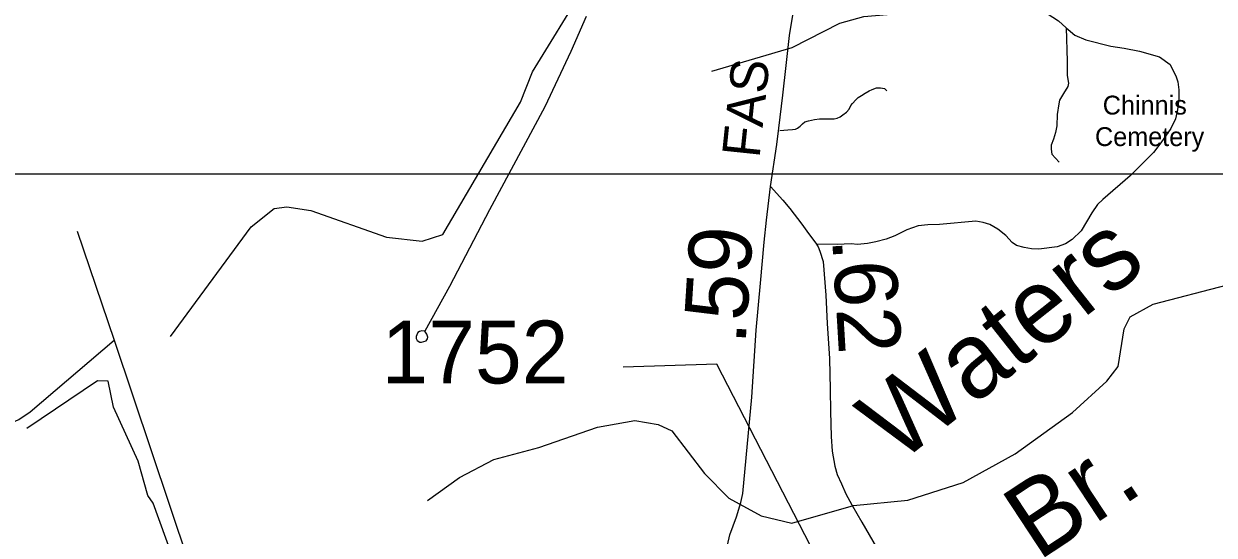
# Model space of a CAD drawing. Extents: x 2225501 to 2309677, y 165449 to 227696.
# Drawn here: x 2252503 to 2261977, y 188364 to 192432 of the extents above; entities that cross this region are included whole.
import ezdxf

# ---------------------------------------------------------------- set-up
doc = ezdxf.new("R2010")
doc.units = 0
for name, color, linetype in [('E_RDY_CMT_EOP', 7, 'Continuous'), ('Exist Vegetation Text', 7, 'Continuous'), ('Old_Level_3', 7, 'Continuous'), ('Old_Level_33', 7, 'Continuous'), ('Old_Level_50', 7, 'Continuous'), ('P_HYD_Drop_Inlet_Grate_2_Narrow_Slots_and_Sag_Grates_840_24_54_Dia_CELL', 7, 'Continuous'), ('P_HYD_Endwall_838_01_18_Dia_Single-Top_CELL', 7, 'Continuous'), ('P_HYD_Pipe_Pipe_Removal', 7, 'Continuous'), ('P_RDY_Dimension_Text', 7, 'Continuous'), ('Prop Support', 7, 'Continuous'), ('Scratch_Level_1', 7, 'Continuous'), ('Scratch_Level_7', 7, 'Continuous'), ('Typical Terminator CELL', 7, 'Continuous')]:
    doc.layers.add(name, color=color, linetype=linetype)

msp = doc.modelspace()

# ---------------------------------------------------------------- linework, layer by layer
at = {"layer": 'Old_Level_3'}
for p, q in [((2252926.7, 190782.9), (2253221.5, 189915.8)), ((2253221.5, 189915.8), (2253929.5, 187811.9))]:
    msp.add_line(p, q, dxfattribs=at)
for points in [[(2258940.7, 193185.2), (2259378.5, 193157.6), (2259462.9, 193157.6), (2259535.6, 193148.9), (2259608.3, 193119.8), (2259695.5, 193079.1), (2259983.5, 192924.9), (2260184.1, 192817.2), (2260285.9, 192756.1), (2260422.6, 192663), (2260737.8, 192456.1), (2260797.9, 192401.8)], [(2256979, 192491.4), (2256855.4, 192212.6), (2256649, 191771), (2256208, 190953.7), (2255891, 190343.5), (2255694.1, 189986)], [(2260797.9, 192401.8), (2260814.4, 192386.8), (2260868.8, 192343.2), (2260955, 192303.9), (2261155.4, 192255.6), (2261261.4, 192238.6), (2261383.5, 192213.6), (2261541.9, 192170.9), (2261626.4, 192109.5), (2261675.1, 192012), (2261687.5, 191972.1), (2261696.1, 191906.2), (2261694.5, 191838.2), (2261685.4, 191748.2), (2261668, 191676), (2261632.5, 191599.9), (2261553.5, 191485.3), (2261494.2, 191408.8), (2261307.6, 191223.3), (2261089.4, 191035.6), (2261047.6, 190995.2), (2261004.2, 190928.9), (2260917.4, 190784.2), (2260846, 190715.6), (2260792.4, 190681.3), (2260726.6, 190658.8), (2260580.8, 190639.6), (2260522.7, 190643.1), (2260464.7, 190652.7), (2260404.7, 190670), (2260368.3, 190693.7), (2260318, 190747.3), (2260255.6, 190798.9), (2260191.4, 190836.4), (2260139.3, 190852), (2260081.1, 190861.5), (2259791.4, 190835.1), (2259697.6, 190832.4), (2259619.7, 190825.7), (2259529.9, 190792.9), (2259436.4, 190746.3), (2259366.7, 190719.6), (2259284.9, 190697), (2259219, 190684.5), (2259137.1, 190677.7), (2259087, 190681.3), (2258975.1, 190676.5), (2258811.2, 190679.1)], [(2260797.9, 192401.8), (2260808, 192136.4), (2260808, 192020.1), (2260816.7, 191959), (2260810.9, 191932.8), (2260778.9, 191877.5), (2260746.9, 191825.1), (2260741.1, 191796), (2260726.5, 191711.7), (2260723.6, 191621.5), (2260714.9, 191569.1), (2260697.4, 191513.8), (2260680, 191467.3), (2260680, 191435.3), (2260685.8, 191394.6), (2260744, 191330.6)], [(2258520.5, 191583.4), (2258583.1, 191588.8), (2258620.9, 191591.7), (2258644.2, 191594.6), (2258660.2, 191601.9), (2258680.5, 191617.9), (2258700.9, 191636.8), (2258719.8, 191652.8), (2258748.9, 191661.5), (2258796.9, 191670.2), (2258836.1, 191676), (2258879.8, 191677.5), (2258923.4, 191677.5), (2258952.5, 191677.5), (2258977.2, 191681.9), (2259000.5, 191692), (2259022.3, 191708), (2259049.9, 191729.9), (2259071.7, 191754.6), (2259086.3, 191782.2), (2259097.9, 191799.7), (2259124.1, 191828.8), (2259144.4, 191846.2), (2259169.1, 191862.2), (2259199.7, 191879.7), (2259230.2, 191898.6), (2259254.9, 191910.2), (2259289.8, 191921.9), (2259320.4, 191923.3), (2259353.8, 191917.5), (2259372.7, 191898.6)], [(2255694.1, 189986), (2255669.9, 189989.6), (2255652, 189983.6), (2255640.1, 189975.4), (2255630.4, 189959.4), (2255626.5, 189945.3), (2255626.6, 189929.3), (2255634.7, 189913.6), (2255654.8, 189899.6), (2255666.8, 189899.7), (2255704.6, 189910), (2255716.5, 189926.2), (2255718.4, 189940.1), (2255710.2, 189962.1), (2255694.1, 189986)], [(2252411.3, 189261.4), (2252463, 189283.9), (2252554.5, 189346.5), (2253221.5, 189915.8)]]:
    msp.add_lwpolyline(points, dxfattribs=at)
at = {"layer": 'Old_Level_33'}
msp.add_lwpolyline([(2258446.3, 191137), (2258544.3, 191028.8), (2258600.3, 190962.2), (2258694.3, 190839.1), (2258748.6, 190764.9), (2258807.4, 190686.1), (2258825.5, 190657.2), (2258839.5, 190623.3), (2258865.3, 190541.3), (2258887, 190273.5), (2258897.9, 190049), (2258916.5, 189770.2), (2258921.4, 189522.3), (2258922, 189348.6), (2258927.5, 189148.6), (2258936.5, 189032.8), (2258957.6, 188914.1), (2258977.5, 188847.2), (2259010, 188773), (2259044.4, 188693.3), (2259093.3, 188604.6), (2259172.9, 188467.1), (2259288.7, 188266.2), (2259355, 188119.2)], dxfattribs=at)
at = {"layer": 'Old_Level_50'}
for points in [[(2258446.3, 191137), (2258496.5, 191471.5), (2258512.9, 191603.5), (2258543.7, 191866), (2258569.6, 192100.7), (2258595.8, 192338.5), (2258629.6, 192532.4)], [(2258048.1, 188044.7), (2258075.7, 188167.2), (2258122.3, 188366.4), (2258175.1, 188510.8), (2258210.1, 188623.1), (2258225.5, 188695.2), (2258297.2, 189461.4), (2258331.4, 189994.9), (2258364.8, 190369.4), (2258394.9, 190695.5), (2258415, 190871), (2258446.3, 191137)]]:
    msp.add_lwpolyline(points, dxfattribs=at)
at = {"layer": 'P_HYD_Endwall_838_01_18_Dia_Single-Top_CELL'}
msp.add_lwpolyline([(2258763.7, 188280), (2258018.3, 189724.1), (2257272.6, 189702.1)], dxfattribs=at)
at = {"layer": 'P_HYD_Pipe_Pipe_Removal'}
msp.add_lwpolyline([(2243855.6, 191238), (2266253.9, 191238), (2266253.9, 223233.6), (2243855.6, 223233.6)], close=True, dxfattribs=at)
at = {"layer": 'Prop Support'}
for points in [[(2253671.7, 189944.7), (2254313.7, 190817.8), (2254496.6, 190961.9), (2254595.6, 190976.4), (2254787.8, 190946.4), (2255389.6, 190734.6), (2255672.8, 190702.8), (2255838.7, 190755.4), (2256455.7, 191809.4), (2256552.7, 192050.2), (2256963.8, 192721.2), (2257045.8, 192982), (2257283.7, 193423.5), (2257370.8, 193992.5), (2257359.7, 194291.2), (2257248.8, 194549.2), (2257150.8, 195322), (2257108.8, 195372), (2257123.7, 195581.6), (2257304.8, 195873.3), (2257554.7, 196498.2)], [(2254486.8, 183988.5), (2254415.6, 184537.7), (2254436.7, 185019.4), (2254516.7, 185405), (2254531.7, 185588.3), (2254506.6, 185611.8), (2254487.6, 185936.9), (2254214.7, 186627.7), (2254196.6, 186792.1), (2254001.6, 187225.6), (2253966.7, 187416.6), (2253532.6, 188618.9), (2253489.6, 188678.8), (2253412.7, 188952.6), (2253217.7, 189382.8), (2253174.6, 189590.3), (2253090.6, 189591.9), (2252527.7, 189212.5)]]:
    msp.add_lwpolyline(points, dxfattribs=at)
at = {"layer": 'Typical Terminator CELL'}
for points in [[(2257977.8, 192055.3), (2258617.7, 192242.9), (2258998.7, 192438.9), (2259189.8, 192490.9), (2260147.8, 192573.9), (2260288.7, 192607.3), (2260512.8, 192750.5), (2260677.7, 192927.7), (2260975.8, 193105.6), (2261308.8, 193158.1), (2262466.8, 193207.8)], [(2255714.6, 188638.8), (2255971.7, 188824.1), (2256244.7, 188966.3), (2256602.7, 189061.1), (2257067.7, 189222.6), (2257366.7, 189275.8), (2257550.6, 189246), (2257659.7, 189194.7), (2257920.8, 188855), (2258113.7, 188657.7), (2258372.7, 188518.2), (2258614.7, 188461), (2259105.8, 188599.1), (2259537.8, 188643.2), (2259978.7, 188782.2), (2260392.7, 189010.3), (2260848.7, 189339.2), (2261121.8, 189589.8), (2261211.8, 189706.1), (2261259.8, 190007), (2261308.8, 190101.1), (2261491.7, 190202.5), (2262081.9, 190355.1)]]:
    msp.add_lwpolyline(points, dxfattribs=at)

# ---------------------------------------------------------------- texts
at = {"layer": 'E_RDY_CMT_EOP'}
msp.add_text('1752', height=500, dxfattribs=at).set_placement((2255350.1, 189571.3))
at = {"layer": 'Exist Vegetation Text'}
for s, p in [('Chinnis', (2261090, 191710.9)), ('Cemetery', (2261028.4, 191459.9))]:
    msp.add_text(s, height=150, dxfattribs=at).set_placement(p)
at = {"layer": 'P_HYD_Drop_Inlet_Grate_2_Narrow_Slots_and_Sag_Grates_840_24_54_Dia_CELL'}
msp.add_text('FAS', height=300, rotation=84.03063, dxfattribs=at).set_placement((2258357.6, 191359.6))
at = {"layer": 'P_RDY_Dimension_Text'}
msp.add_text('.62', height=500, rotation=273.41422, dxfattribs=at).set_placement((2258935.9, 190723))
at = {"layer": 'Scratch_Level_1'}
for s, rotation, p in [('Waters', 38.31916, (2259461.4, 188921.6)), ('Br.', 33.36011, (2260575, 188152.5))]:
    msp.add_text(s, height=600, rotation=rotation, dxfattribs=at).set_placement(p)
at = {"layer": 'Scratch_Level_7'}
msp.add_text('.59', height=500, rotation=86.33056, dxfattribs=at).set_placement((2258246.6, 189876.4))

doc.saveas('drawing.dxf')
